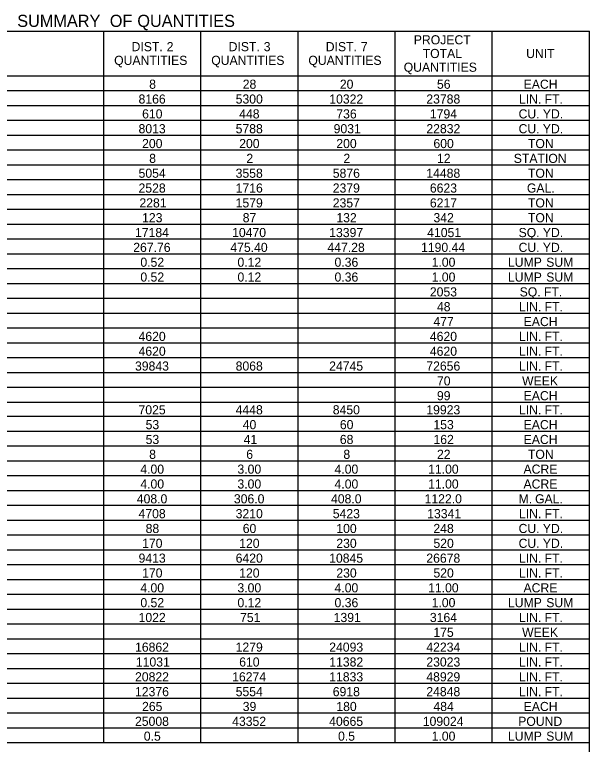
# Model space of a CAD drawing. Extents: x 544250 to 1930787, y -1948365 to 596640.
# Drawn here: x 558238.2 to 558616.2, y -1947939.8 to -1947460.1 of the extents above; entities that cross this region are included whole.
import ezdxf

# ---------------------------------------------------------------- set-up
doc = ezdxf.new("R2010")
doc.units = 0
doc.layers.add('Default', color=7, linetype='Continuous')

msp = doc.modelspace()

# ---------------------------------------------------------------- linework, layer by layer
at = {"layer": 'Default'}
for p, q in [((557865.48, -1947471.02), (558616.23, -1947471.02)), ((558296.92, -1947938.53), (558296.92, -1947471.02)), ((558360.78, -1947938.53), (558360.78, -1947471.02)), ((558360.78, -1947500.27), (558360.78, -1947471.02)), ((558424.64, -1947938.53), (558424.64, -1947471.02)), ((558424.64, -1947500.27), (558424.64, -1947471.02)), ((558488.51, -1947938.53), (558488.51, -1947471.02)), ((558552.37, -1947938.53), (558552.37, -1947471.02)), ((558552.37, -1947938.53), (558552.37, -1947471.02)), ((558616.23, -1948065.28), (558616.23, -1947471.02)), ((557865.48, -1947500.27), (558616.23, -1947500.27)), ((557865.48, -1947500.27), (558616.23, -1947500.27)), ((558296.92, -1947811.78), (558296.92, -1947500.27)), ((557865.48, -1947510.02), (558616.23, -1947510.02)), ((557865.48, -1947519.77), (558616.23, -1947519.77)), ((557865.48, -1947529.52), (558616.23, -1947529.52)), ((557865.48, -1947539.27), (558616.23, -1947539.27)), ((557865.48, -1947549.02), (558616.23, -1947549.02)), ((557865.48, -1947558.77), (558616.23, -1947558.77)), ((557865.48, -1947568.52), (558616.23, -1947568.52)), ((557865.48, -1947578.27), (558616.23, -1947578.27)), ((557865.48, -1947588.02), (558616.23, -1947588.02)), ((557865.48, -1947597.77), (558616.23, -1947597.77)), ((557865.48, -1947607.52), (558616.23, -1947607.52)), ((557865.48, -1947617.27), (558616.23, -1947617.27)), ((557865.48, -1947627.02), (558616.23, -1947627.02)), ((557865.48, -1947636.77), (558616.23, -1947636.77)), ((557865.48, -1947646.52), (558616.23, -1947646.52)), ((557865.48, -1947656.27), (558616.23, -1947656.27)), ((557865.48, -1947666.02), (558616.23, -1947666.02)), ((557865.48, -1947675.77), (558616.23, -1947675.77)), ((557865.48, -1947685.52), (558616.23, -1947685.52)), ((557865.48, -1947695.27), (558616.23, -1947695.27)), ((557865.48, -1947705.02), (558616.23, -1947705.02)), ((557865.48, -1947714.77), (558616.23, -1947714.77)), ((557865.48, -1947724.03), (558616.23, -1947724.03)), ((557865.48, -1947733.78), (558616.23, -1947733.78)), ((557865.48, -1947743.53), (558616.23, -1947743.53)), ((557865.48, -1947753.28), (558616.23, -1947753.28)), ((557865.48, -1947763.03), (558616.23, -1947763.03)), ((557865.48, -1947772.78), (558616.23, -1947772.78)), ((557865.48, -1947782.53), (558616.23, -1947782.53)), ((557865.48, -1947792.28), (558616.23, -1947792.28)), ((557865.48, -1947802.03), (558616.23, -1947802.03)), ((557865.48, -1947811.78), (558616.23, -1947811.78)), ((557865.48, -1947821.53), (558616.23, -1947821.53)), ((558296.92, -1947938.53), (558296.92, -1947821.53)), ((558552.37, -1947821.53), (558616.23, -1947821.53)), ((557865.48, -1947831.28), (558616.23, -1947831.28)), ((557865.48, -1947841.03), (558616.23, -1947841.03)), ((557865.48, -1947850.78), (558616.23, -1947850.78)), ((557865.48, -1947860.53), (558616.23, -1947860.53)), ((557865.48, -1947870.28), (558616.23, -1947870.28)), ((557865.48, -1947880.03), (558616.23, -1947880.03)), ((557865.48, -1947889.78), (558616.23, -1947889.78)), ((557865.48, -1947899.53), (558616.23, -1947899.53)), ((557865.48, -1947909.28), (558616.23, -1947909.28)), ((557865.48, -1947919.03), (558616.23, -1947919.03)), ((557865.48, -1947928.78), (558616.23, -1947928.78)), ((557865.48, -1947938.53), (558616.23, -1947938.53)), ((558235.98, -1947938.53), (558296.92, -1947938.53)), ((558296.92, -1947938.53), (558616.23, -1947938.53))]:
    msp.add_line(p, q, dxfattribs=at)

# ---------------------------------------------------------------- texts
for s, height, p in [(' SUMMARY', 8, (558236.96, -1947468.19)), (' OF', 8, (558297.84, -1947468.19)), (' QUANTITIES', 8, (558315.95, -1947468.19)), ('PROJECT', 6, (558500.73, -1947479.64)), ('DIST.', 6, (558315.14, -1947484.14)), (' 2', 6, (558335.99, -1947484.14)), ('DIST.', 6, (558378.98, -1947484.14)), (' 3', 6, (558399.82, -1947484.14)), ('DIST.', 6, (558442.84, -1947484.14)), (' 7', 6, (558463.69, -1947484.14)), ('TOTAL', 6, (558506.59, -1947488.64)), ('UNIT', 6, (558574.61, -1947488.64)), ('QUANTITIES', 6, (558303.67, -1947493.14)), ('QUANTITIES', 6, (558367.53, -1947493.14)), ('QUANTITIES', 6, (558431.4, -1947493.14)), ('QUANTITIES', 6, (558494.09, -1947497.64)), ('8', 6, (558326.71, -1947508.82)), ('28', 6, (558388.24, -1947508.82)), ('20', 6, (558452.12, -1947508.82)), ('56', 6, (558515.97, -1947508.82)), ('EACH', 6, (558572.99, -1947508.82)), ('8166', 6, (558319.72, -1947518.57)), ('5300', 6, (558383.59, -1947518.57)), ('10322', 6, (558445.15, -1947518.57)), ('23788', 6, (558508.97, -1947518.57)), ('LIN.', 6, (558569.9, -1947518.57)), (' FT.', 6, (558584.54, -1947518.57)), ('610', 6, (558322.06, -1947528.32)), ('448', 6, (558385.91, -1947528.32)), ('736', 6, (558449.78, -1947528.32)), ('1794', 6, (558511.32, -1947528.32)), ('CU.', 6, (558569.66, -1947528.32)), (' YD.', 6, (558583.37, -1947528.32)), ('8013', 6, (558319.72, -1947538.07)), ('5788', 6, (558383.58, -1947538.07)), ('9031', 6, (558448.03, -1947538.07)), ('22832', 6, (558509.01, -1947538.07)), ('CU.', 6, (558569.66, -1947538.07)), (' YD.', 6, (558583.37, -1947538.07)), ('200', 6, (558322.06, -1947547.82)), ('200', 6, (558385.92, -1947547.82)), ('200', 6, (558449.79, -1947547.82)), ('600', 6, (558513.65, -1947547.82)), ('TON', 6, (558575.8, -1947547.82)), ('8', 6, (558326.71, -1947557.57)), ('2', 6, (558390.61, -1947557.57)), ('2', 6, (558454.47, -1947557.57)), ('12', 6, (558516, -1947557.57)), ('STATION', 6, (558566.48, -1947557.57)), ('5054', 6, (558319.73, -1947567.32)), ('3558', 6, (558383.58, -1947567.32)), ('5876', 6, (558447.45, -1947567.32)), ('14488', 6, (558508.97, -1947567.32)), ('TON', 6, (558575.8, -1947567.32)), ('2528', 6, (558319.72, -1947577.07)), ('1716', 6, (558383.58, -1947577.07)), ('2379', 6, (558447.44, -1947577.07)), ('6623', 6, (558511.31, -1947577.07)), ('GAL.', 6, (558575.12, -1947577.07)), ('2281', 6, (558320.3, -1947586.82)), ('1579', 6, (558383.58, -1947586.82)), ('2357', 6, (558447.45, -1947586.82)), ('6217', 6, (558511.31, -1947586.82)), ('TON', 6, (558575.8, -1947586.82)), ('123', 6, (558322.05, -1947596.57)), ('87', 6, (558388.24, -1947596.57)), ('132', 6, (558449.81, -1947596.57)), ('342', 6, (558513.67, -1947596.57)), ('TON', 6, (558575.8, -1947596.57)), ('17184', 6, (558317.4, -1947606.32)), ('10470', 6, (558381.26, -1947606.32)), ('13397', 6, (558445.12, -1947606.32)), ('41051', 6, (558509.56, -1947606.32)), ('SQ.', 6, (558569.66, -1947606.32)), (' YD.', 6, (558583.37, -1947606.32)), ('267.76', 6, (558316.23, -1947616.07)), ('475.40', 6, (558380.1, -1947616.07)), ('447.28', 6, (558443.95, -1947616.07)), ('1190.44', 6, (558505.5, -1947616.07)), ('CU.', 6, (558569.66, -1947616.07)), (' YD.', 6, (558583.37, -1947616.07)), ('0.52', 6, (558320.92, -1947625.82)), ('0.12', 6, (558384.78, -1947625.82)), ('0.36', 6, (558448.61, -1947625.82)), ('1.00', 6, (558512.49, -1947625.82)), ('LUMP', 6, (558562.67, -1947625.82)), (' SUM', 6, (558585.6, -1947625.82)), ('0.52', 6, (558320.92, -1947635.57)), ('0.12', 6, (558384.78, -1947635.57)), ('0.36', 6, (558448.61, -1947635.57)), ('1.00', 6, (558512.49, -1947635.57)), ('LUMP', 6, (558562.67, -1947635.57)), (' SUM', 6, (558585.6, -1947635.57)), ('2053', 6, (558511.31, -1947645.32)), ('SQ.', 6, (558570.36, -1947645.32)), (' FT.', 6, (558584.07, -1947645.32)), ('48', 6, (558515.96, -1947655.07)), ('LIN.', 6, (558569.9, -1947655.07)), (' FT.', 6, (558584.54, -1947655.07)), ('477', 6, (558513.64, -1947664.82)), ('EACH', 6, (558572.99, -1947664.82)), ('4620', 6, (558319.73, -1947674.57)), ('4620', 6, (558511.32, -1947674.57)), ('LIN.', 6, (558569.9, -1947674.57)), (' FT.', 6, (558584.54, -1947674.57)), ('4620', 6, (558319.73, -1947684.32)), ('4620', 6, (558511.32, -1947684.32)), ('LIN.', 6, (558569.9, -1947684.32)), (' FT.', 6, (558584.54, -1947684.32)), ('39843', 6, (558317.39, -1947694.07)), ('8068', 6, (558383.58, -1947694.07)), ('24745', 6, (558445.09, -1947694.07)), ('72656', 6, (558508.98, -1947694.07)), ('LIN.', 6, (558569.9, -1947694.07)), (' FT.', 6, (558584.54, -1947694.07)), ('70', 6, (558515.98, -1947703.82)), ('WEEK', 6, (558571.96, -1947703.82)), ('99', 6, (558515.96, -1947713.57)), ('EACH', 6, (558572.99, -1947713.57)), ('7025', 6, (558319.7, -1947722.83)), ('4448', 6, (558383.58, -1947722.83)), ('8450', 6, (558447.46, -1947722.83)), ('19923', 6, (558508.98, -1947722.83)), ('LIN.', 6, (558569.9, -1947722.83)), (' FT.', 6, (558584.54, -1947722.83)), ('53', 6, (558324.38, -1947732.58)), ('40', 6, (558388.25, -1947732.58)), ('60', 6, (558452.12, -1947732.58)), ('153', 6, (558513.64, -1947732.58)), ('EACH', 6, (558572.99, -1947732.58)), ('53', 6, (558324.38, -1947742.33)), ('41', 6, (558388.82, -1947742.33)), ('68', 6, (558452.1, -1947742.33)), ('162', 6, (558513.67, -1947742.33)), ('EACH', 6, (558572.99, -1947742.33)), ('8', 6, (558326.71, -1947752.08)), ('6', 6, (558390.57, -1947752.08)), ('8', 6, (558454.43, -1947752.08)), ('22', 6, (558516, -1947752.08)), ('TON', 6, (558575.8, -1947752.08)), ('4.00', 6, (558320.9, -1947761.83)), ('3.00', 6, (558384.76, -1947761.83)), ('4.00', 6, (558448.62, -1947761.83)), ('11.00', 6, (558510.16, -1947761.83)), ('ACRE', 6, (558572.88, -1947761.83)), ('4.00', 6, (558320.9, -1947771.58)), ('3.00', 6, (558384.76, -1947771.58)), ('4.00', 6, (558448.62, -1947771.58)), ('11.00', 6, (558510.16, -1947771.58)), ('ACRE', 6, (558572.88, -1947771.58)), ('408.0', 6, (558318.57, -1947781.33)), ('306.0', 6, (558382.43, -1947781.33)), ('408.0', 6, (558446.29, -1947781.33)), ('1122.0', 6, (558507.83, -1947781.33)), ('M.', 6, (558569.66, -1947781.33)), (' GAL.', 6, (558578.24, -1947781.33)), ('4708', 6, (558319.72, -1947791.08)), ('3210', 6, (558383.59, -1947791.08)), ('5423', 6, (558447.45, -1947791.08)), ('13341', 6, (558509.56, -1947791.08)), ('LIN.', 6, (558569.9, -1947791.08)), (' FT.', 6, (558584.54, -1947791.08)), ('88', 6, (558324.38, -1947800.83)), ('60', 6, (558388.25, -1947800.83)), ('100', 6, (558449.79, -1947800.83)), ('248', 6, (558513.63, -1947800.83)), ('CU.', 6, (558569.66, -1947800.83)), (' YD.', 6, (558583.37, -1947800.83)), ('170', 6, (558322.06, -1947810.58)), ('120', 6, (558385.92, -1947810.58)), ('230', 6, (558449.79, -1947810.58)), ('520', 6, (558513.65, -1947810.58)), ('CU.', 6, (558569.66, -1947810.58)), (' YD.', 6, (558583.37, -1947810.58)), ('9413', 6, (558319.72, -1947820.33)), ('6420', 6, (558383.59, -1947820.33)), ('10845', 6, (558445.09, -1947820.33)), ('26678', 6, (558508.97, -1947820.33)), ('LIN.', 6, (558569.9, -1947820.33)), (' FT.', 6, (558584.54, -1947820.33)), ('170', 6, (558322.06, -1947830.08)), ('120', 6, (558385.92, -1947830.08)), ('230', 6, (558449.79, -1947830.08)), ('520', 6, (558513.65, -1947830.08)), ('LIN.', 6, (558569.9, -1947830.08)), (' FT.', 6, (558584.54, -1947830.08)), ('4.00', 6, (558320.9, -1947839.83)), ('3.00', 6, (558384.76, -1947839.83)), ('4.00', 6, (558448.62, -1947839.83)), ('11.00', 6, (558510.16, -1947839.83)), ('ACRE', 6, (558572.88, -1947839.83)), ('0.52', 6, (558320.92, -1947849.58)), ('0.12', 6, (558384.78, -1947849.58)), ('0.36', 6, (558448.61, -1947849.58)), ('1.00', 6, (558512.49, -1947849.58)), ('LUMP', 6, (558562.67, -1947849.58)), (' SUM', 6, (558585.6, -1947849.58)), ('1022', 6, (558319.75, -1947859.33)), ('751', 6, (558386.49, -1947859.33)), ('1391', 6, (558448.03, -1947859.33)), ('3164', 6, (558511.32, -1947859.33)), ('LIN.', 6, (558569.9, -1947859.33)), (' FT.', 6, (558584.54, -1947859.33)), ('175', 6, (558513.62, -1947869.08)), ('WEEK', 6, (558571.96, -1947869.08)), ('16862', 6, (558317.42, -1947878.83)), ('1279', 6, (558383.58, -1947878.83)), ('24093', 6, (558445.12, -1947878.83)), ('42234', 6, (558508.99, -1947878.83)), ('LIN.', 6, (558569.9, -1947878.83)), (' FT.', 6, (558584.54, -1947878.83)), ('11031', 6, (558317.97, -1947888.58)), ('610', 6, (558385.92, -1947888.58)), ('11382', 6, (558445.15, -1947888.58)), ('23023', 6, (558508.98, -1947888.58)), ('LIN.', 6, (558569.9, -1947888.58)), (' FT.', 6, (558584.54, -1947888.58)), ('20822', 6, (558317.42, -1947898.33)), ('16274', 6, (558381.27, -1947898.33)), ('11833', 6, (558445.12, -1947898.33)), ('48929', 6, (558508.97, -1947898.33)), ('LIN.', 6, (558569.9, -1947898.33)), (' FT.', 6, (558584.54, -1947898.33)), ('12376', 6, (558317.39, -1947908.08)), ('5554', 6, (558383.6, -1947908.08)), ('6918', 6, (558447.44, -1947908.08)), ('24848', 6, (558508.97, -1947908.08)), ('LIN.', 6, (558569.9, -1947908.08)), (' FT.', 6, (558584.54, -1947908.08)), ('265', 6, (558322.03, -1947917.83)), ('39', 6, (558388.24, -1947917.83)), ('180', 6, (558449.79, -1947917.83)), ('484', 6, (558513.65, -1947917.83)), ('EACH', 6, (558572.99, -1947917.83)), ('25008', 6, (558317.39, -1947927.58)), ('43352', 6, (558381.29, -1947927.58)), ('40665', 6, (558445.09, -1947927.58)), ('109024', 6, (558506.66, -1947927.58)), ('POUND', 6, (558569.39, -1947927.58)), ('0.5', 6, (558323.19, -1947937.33)), ('0.5', 6, (558450.92, -1947937.33)), ('1.00', 6, (558512.49, -1947937.33)), ('LUMP', 6, (558562.67, -1947937.33)), (' SUM', 6, (558585.6, -1947937.33))]:
    msp.add_text(s, height=height, dxfattribs=at).set_placement(p)

doc.saveas('drawing.dxf')
